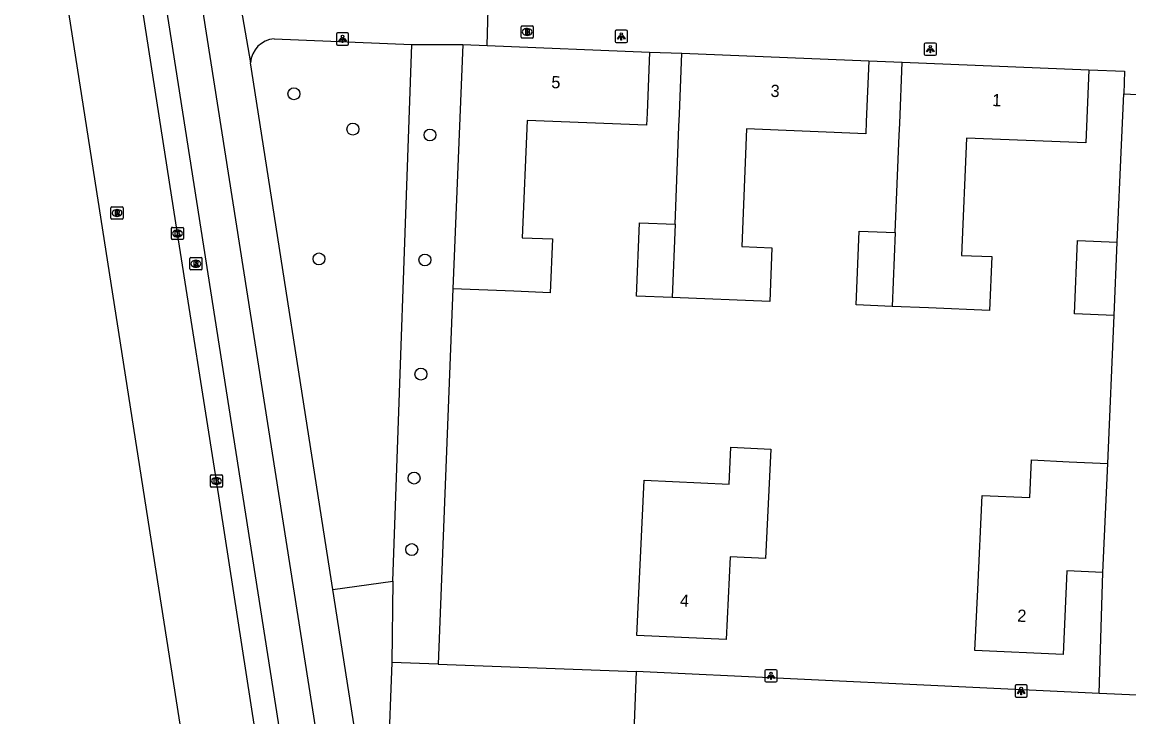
# Model space of a CAD drawing. Extents: x 160787 to 161428, y 386828 to 387483.
# Drawn here: x 160824.8 to 160915.3, y 387157.9 to 387214.7 of the extents above; entities that cross this region are included whole.
import ezdxf

# ---------------------------------------------------------------- set-up
doc = ezdxf.new("R2010")
doc.units = 0
for name, color, linetype in [('IMGEO_Boom', 7, 'Continuous'), ('IMGEO_Brandkraan', 7, 'Continuous'), ('IMGEO_Fietspad_gesloten', 7, 'Continuous'), ('IMGEO_Groenvoorziening', 7, 'Continuous'), ('IMGEO_Kolk', 7, 'Continuous'), ('IMGEO_Lichtpunt', 7, 'Continuous'), ('IMGEO_Muur', 7, 'Continuous'), ('IMGEO_Pand', 7, 'Continuous'), ('IMGEO_Pand_nummerreeks', 7, 'Continuous'), ('IMGEO_Rijbaan_lokaal_gesloten', 7, 'Continuous'), ('IMGEO_Rijbaan_lokaal_open', 7, 'Continuous'), ('IMGEO_Rioolput', 7, 'Continuous'), ('IMGEO_Voetpad_open', 7, 'Continuous')]:
    doc.layers.add(name, color=color, linetype=linetype)

msp = doc.modelspace()

# ---------------------------------------------------------------- linework, layer by layer
at = {"layer": 'IMGEO_Boom'}
for centre in [(160846.992, 387208.88), (160851.817, 387205.988), (160858.126, 387205.51), (160849.043, 387195.369), (160857.713, 387195.286), (160857.388, 387185.951), (160856.826, 387177.451), (160856.63, 387171.6)]:
    msp.add_circle(centre, 0.489, dxfattribs=at)
at = {"layer": 'IMGEO_Brandkraan'}
for p, q in [((160865.581, 387213.511), (160865.581, 387214.363)), ((160865.656, 387214.437), (160866.508, 387214.437)), ((160866.069, 387214.217), (160866.094, 387214.217)), ((160866.582, 387214.363), (160866.582, 387213.511)), ((160866.508, 387213.437), (160865.656, 387213.437)), ((160866.092, 387213.657), (160866.067, 387213.657))]:
    msp.add_line(p, q, dxfattribs=at)
for points in [[(160865.581, 387213.511), (160865.581, 387214.363)], [(160865.656, 387214.437), (160866.508, 387214.437)], [(160866.582, 387214.363), (160866.582, 387213.511)], [(160866.508, 387213.437), (160865.656, 387213.437)], [(160865.929, 387214.137), (160865.929, 387213.737), (160866.142, 387213.737)], [(160866.16, 387214.137), (160865.929, 387214.137)], [(160866.108, 387214.056), (160866.054, 387214.056), (160866.054, 387213.98)], [(160866.054, 387213.98), (160866.107, 387213.98)], [(160866.116, 387213.904), (160866.054, 387213.904), (160866.054, 387213.823)], [(160866.054, 387213.823), (160866.116, 387213.823)]]:
    msp.add_lwpolyline(points, dxfattribs=at)
for centre, radius, start, end in [((160865.658, 387214.361), 0.0765, 91.55205, 178.44795), ((160865.658, 387214.361), 0.0765, 91.55205, 178.44795), ((160866.506, 387214.361), 0.0765, 1.55205, 88.44795), ((160866.506, 387214.361), 0.0765, 1.55205, 88.44795), ((160865.658, 387213.513), 0.0765, 181.55205, 268.44795), ((160865.658, 387213.513), 0.0765, 181.55205, 268.44795), ((160866.109, 387214.018), 0.0379, 267.82845, 90.93552), ((160866.117, 387213.863), 0.0404, 269.87594, 90.50774), ((160866.148, 387213.988), 0.251, 268.66757, 293.53466), ((160866.164, 387213.992), 0.145, 59.4692, 91.53667), ((160866.189, 387214.039), 0.0922, 285.51372, 58.15012), ((160866.194, 387213.847), 0.105, 301.31148, 78.98903), ((160866.506, 387213.513), 0.0765, 271.55205, 358.44795), ((160866.506, 387213.513), 0.0765, 271.55205, 358.44795)]:
    msp.add_arc(centre, radius, start, end, dxfattribs=at)
for centre, major_axis, ratio, start_param, end_param in [((160866.068, 387213.937), (-0.387, 0.002), 0.722429, 4.712389, 7.853982), ((160866.093, 387213.937), (-0.39, 0.002), 0.717154, 1.570796, 4.712389)]:
    msp.add_ellipse(centre, major_axis=major_axis, ratio=ratio, start_param=start_param, end_param=end_param, dxfattribs=at)
at = {"layer": 'IMGEO_Fietspad_gesloten'}
for points in [[(160895.192, 386882.357), (160892.332, 386890.984), (160890.69, 386896.733), (160890.27, 386898.714), (160890.17, 386899.184), (160874.389, 386993.578), (160868.406, 387032.171), (160836.614, 387234.349), (160835.892, 387241.342), (160835.079, 387254.335)], [(160832.411, 387248.937), (160833.16, 387237.408), (160836.374, 387216.975), (160842.596, 387177.288), (160852.187, 387116.071), (160852.723, 387112.646)]]:
    msp.add_lwpolyline(points, dxfattribs=at)
at = {"layer": 'IMGEO_Groenvoorziening'}
for points in [[(160855.085, 387169.007), (160856.628, 387212.906)], [(160859.997, 387192.933), (160858.804, 387162.228)], [(160850.173, 387168.324), (160855.085, 387169.007)], [(160855.085, 387169.007), (160855.009, 387162.37)]]:
    msp.add_lwpolyline(points, dxfattribs=at)
at = {"layer": 'IMGEO_Kolk'}
for p, q in [((160837.037, 387197.957), (160837.889, 387197.957)), ((160836.962, 387197.031), (160836.962, 387197.883)), ((160837.473, 387197.177), (160837.448, 387197.177)), ((160837.45, 387197.737), (160837.475, 387197.737)), ((160837.963, 387197.883), (160837.963, 387197.031)), ((160837.889, 387196.957), (160837.037, 387196.957)), ((160840.156, 387176.784), (160840.156, 387177.636)), ((160840.231, 387177.71), (160841.083, 387177.71)), ((160840.644, 387177.49), (160840.669, 387177.49)), ((160841.157, 387177.636), (160841.157, 387176.784)), ((160841.083, 387176.71), (160840.231, 387176.71)), ((160840.667, 387176.93), (160840.642, 387176.93))]:
    msp.add_line(p, q, dxfattribs=at)
for points in [[(160837.037, 387197.957), (160837.889, 387197.957)], [(160836.962, 387197.031), (160836.962, 387197.883)], [(160837.283, 387197.657), (160837.406, 387197.657), (160837.406, 387197.506), (160837.536, 387197.657), (160837.7, 387197.657), (160837.554, 387197.506), (160837.707, 387197.257), (160837.555, 387197.257), (160837.47, 387197.421), (160837.406, 387197.354), (160837.406, 387197.257), (160837.283, 387197.257), (160837.283, 387197.657)], [(160837.963, 387197.883), (160837.963, 387197.031)], [(160837.889, 387196.957), (160837.037, 387196.957)], [(160840.156, 387176.784), (160840.156, 387177.636)], [(160840.231, 387177.71), (160841.083, 387177.71)], [(160840.477, 387177.41), (160840.6, 387177.41), (160840.6, 387177.259), (160840.73, 387177.41), (160840.894, 387177.41), (160840.748, 387177.259), (160840.901, 387177.01), (160840.749, 387177.01), (160840.664, 387177.174), (160840.6, 387177.107), (160840.6, 387177.01), (160840.477, 387177.01), (160840.477, 387177.41)], [(160841.157, 387177.636), (160841.157, 387176.784)], [(160841.083, 387176.71), (160840.231, 387176.71)]]:
    msp.add_lwpolyline(points, dxfattribs=at)
for centre, start, end in [((160837.039, 387197.881), 91.55205, 178.44795), ((160837.039, 387197.881), 91.55205, 178.44795), ((160837.887, 387197.881), 1.55205, 88.44795), ((160837.887, 387197.881), 1.55205, 88.44795), ((160837.039, 387197.033), 181.55205, 268.44795), ((160837.039, 387197.033), 181.55205, 268.44795), ((160837.887, 387197.033), 271.55205, 358.44795), ((160837.887, 387197.033), 271.55205, 358.44795), ((160840.233, 387177.634), 91.55205, 178.44795), ((160840.233, 387177.634), 91.55205, 178.44795), ((160841.081, 387177.634), 1.55205, 88.44795), ((160841.081, 387177.634), 1.55205, 88.44795), ((160840.233, 387176.786), 181.55205, 268.44795), ((160840.233, 387176.786), 181.55205, 268.44795), ((160841.081, 387176.786), 271.55205, 358.44795), ((160841.081, 387176.786), 271.55205, 358.44795)]:
    msp.add_arc(centre, 0.0765, start, end, dxfattribs=at)
for centre, major_axis, ratio, start_param, end_param in [((160837.449, 387197.457), (-0.387, 0.002), 0.722429, 4.712389, 7.853982), ((160837.474, 387197.457), (-0.39, 0.002), 0.717154, 1.570796, 4.712389), ((160840.643, 387177.21), (-0.387, 0.002), 0.722429, 4.712389, 7.853982), ((160840.668, 387177.21), (-0.39, 0.002), 0.717154, 1.570796, 4.712389)]:
    msp.add_ellipse(centre, major_axis=major_axis, ratio=ratio, start_param=start_param, end_param=end_param, dxfattribs=at)
at = {"layer": 'IMGEO_Lichtpunt'}
for p, q in [((160850.471, 387213.77), (160850.471, 387212.963)), ((160850.471, 387213.77), (160850.471, 387212.963)), ((160851.373, 387213.865), (160850.565, 387213.865)), ((160851.373, 387213.865), (160850.565, 387213.865)), ((160851.467, 387212.963), (160851.467, 387213.77)), ((160851.467, 387212.963), (160851.467, 387213.77)), ((160873.281, 387213.977), (160873.281, 387213.17)), ((160873.281, 387213.977), (160873.281, 387213.17)), ((160874.183, 387214.072), (160873.375, 387214.072)), ((160874.183, 387214.072), (160873.375, 387214.072)), ((160874.277, 387213.17), (160874.277, 387213.977)), ((160874.277, 387213.17), (160874.277, 387213.977)), ((160850.565, 387212.869), (160851.373, 387212.869)), ((160850.565, 387212.869), (160851.373, 387212.869)), ((160873.375, 387213.076), (160874.183, 387213.076)), ((160873.375, 387213.076), (160874.183, 387213.076)), ((160898.568, 387212.93), (160898.568, 387212.123)), ((160898.568, 387212.93), (160898.568, 387212.123)), ((160899.47, 387213.025), (160898.662, 387213.025)), ((160899.47, 387213.025), (160898.662, 387213.025)), ((160899.564, 387212.123), (160899.564, 387212.93)), ((160899.564, 387212.123), (160899.564, 387212.93)), ((160898.662, 387212.029), (160899.47, 387212.029)), ((160898.662, 387212.029), (160899.47, 387212.029)), ((160885.535, 387161.674), (160885.535, 387160.867)), ((160885.535, 387161.674), (160885.535, 387160.867)), ((160886.437, 387161.769), (160885.629, 387161.769)), ((160886.437, 387161.769), (160885.629, 387161.769)), ((160886.531, 387160.867), (160886.531, 387161.674)), ((160886.531, 387160.867), (160886.531, 387161.674)), ((160885.629, 387160.773), (160886.437, 387160.773)), ((160885.629, 387160.773), (160886.437, 387160.773)), ((160906.005, 387160.437), (160906.005, 387159.63)), ((160906.005, 387160.437), (160906.005, 387159.63)), ((160906.907, 387160.532), (160906.099, 387160.532)), ((160906.907, 387160.532), (160906.099, 387160.532)), ((160907.001, 387159.63), (160907.001, 387160.437)), ((160907.001, 387159.63), (160907.001, 387160.437)), ((160906.099, 387159.536), (160906.907, 387159.536)), ((160906.099, 387159.536), (160906.907, 387159.536))]:
    msp.add_line(p, q, dxfattribs=at)
for points in [[(160850.845, 387213.434), (160850.884, 387213.406), (160850.696, 387213.144), (160850.658, 387213.171), (160850.845, 387213.434)], [(160850.947, 387213.386), (160850.994, 387213.386), (160850.994, 387213.064), (160850.947, 387213.064), (160850.947, 387213.386)], [(160851.057, 387213.406), (160851.095, 387213.433), (160851.282, 387213.171), (160851.243, 387213.143), (160851.057, 387213.406)], [(160873.655, 387213.641), (160873.694, 387213.613), (160873.506, 387213.351), (160873.468, 387213.378), (160873.655, 387213.641)], [(160873.757, 387213.593), (160873.804, 387213.593), (160873.804, 387213.271), (160873.757, 387213.271), (160873.757, 387213.593)], [(160873.867, 387213.613), (160873.905, 387213.64), (160874.092, 387213.378), (160874.053, 387213.35), (160873.867, 387213.613)], [(160898.942, 387212.594), (160898.981, 387212.566), (160898.793, 387212.304), (160898.755, 387212.331), (160898.942, 387212.594)], [(160899.044, 387212.546), (160899.091, 387212.546), (160899.091, 387212.224), (160899.044, 387212.224), (160899.044, 387212.546)], [(160899.154, 387212.566), (160899.192, 387212.593), (160899.379, 387212.331), (160899.34, 387212.303), (160899.154, 387212.566)], [(160885.909, 387161.338), (160885.948, 387161.31), (160885.76, 387161.048), (160885.722, 387161.075), (160885.909, 387161.338)], [(160886.011, 387161.29), (160886.058, 387161.29), (160886.058, 387160.968), (160886.011, 387160.968), (160886.011, 387161.29)], [(160886.121, 387161.31), (160886.159, 387161.337), (160886.346, 387161.075), (160886.307, 387161.047), (160886.121, 387161.31)], [(160906.379, 387160.101), (160906.418, 387160.073), (160906.23, 387159.811), (160906.192, 387159.838), (160906.379, 387160.101)], [(160906.481, 387160.053), (160906.528, 387160.053), (160906.528, 387159.731), (160906.481, 387159.731), (160906.481, 387160.053)], [(160906.591, 387160.073), (160906.629, 387160.1), (160906.816, 387159.838), (160906.777, 387159.81), (160906.591, 387160.073)]]:
    msp.add_lwpolyline(points, dxfattribs=at)
for centre in [(160850.97, 387213.568), (160873.78, 387213.775), (160899.067, 387212.728), (160886.034, 387161.472), (160906.504, 387160.235)]:
    msp.add_circle(centre, 0.0994, dxfattribs=at)
for centre, start, end in [((160850.565, 387213.77), 90, 180), ((160850.565, 387213.77), 90, 180), ((160851.373, 387213.77), 0, 90), ((160851.373, 387213.77), 0, 90), ((160873.375, 387213.977), 90, 180), ((160873.375, 387213.977), 90, 180), ((160874.183, 387213.977), 0, 90), ((160874.183, 387213.977), 0, 90), ((160850.565, 387212.963), 180, 270), ((160850.565, 387212.963), 180, 270), ((160851.373, 387212.963), 270, 0), ((160851.373, 387212.963), 270, 360), ((160873.375, 387213.17), 180, 270), ((160873.375, 387213.17), 180, 270), ((160874.183, 387213.17), 270, 0), ((160874.183, 387213.17), 270, 360), ((160898.662, 387212.93), 90, 180), ((160898.662, 387212.93), 90, 180), ((160899.47, 387212.93), 0, 90), ((160899.47, 387212.93), 0, 90), ((160898.662, 387212.123), 180, 270), ((160898.662, 387212.123), 180, 270), ((160899.47, 387212.123), 270, 0), ((160899.47, 387212.123), 270, 360), ((160885.629, 387161.674), 90, 180), ((160885.629, 387161.674), 90, 180), ((160886.437, 387161.674), 0, 90), ((160886.437, 387161.674), 0, 90), ((160885.629, 387160.867), 180, 270), ((160885.629, 387160.867), 180, 270), ((160886.437, 387160.867), 270, 0), ((160886.437, 387160.867), 270, 360), ((160906.099, 387160.437), 90, 180), ((160906.099, 387160.437), 90, 180), ((160906.907, 387160.437), 0, 90), ((160906.907, 387160.437), 0, 90), ((160906.099, 387159.63), 180, 270), ((160906.099, 387159.63), 180, 270), ((160906.907, 387159.63), 270, 0), ((160906.907, 387159.63), 270, 360)]:
    msp.add_arc(centre, 0.0946, start, end, dxfattribs=at)
at = {"layer": 'IMGEO_Muur'}
msp.add_lwpolyline([(160914.724, 387204.715), (160914.892, 387208.871)], dxfattribs=at)
at = {"layer": 'IMGEO_Pand'}
for points in [[(160860.807, 387212.918), (160859.997, 387192.933)], [(160860.807, 387212.918), (160862.811, 387212.837)], [(160862.811, 387212.837), (160876.089, 387212.298)], [(160876.089, 387212.298), (160875.887, 387207.303), (160875.846, 387206.302), (160866.068, 387206.699), (160865.68, 387197.108), (160868.14, 387197.009), (160867.961, 387192.611), (160864.993, 387192.731), (160859.997, 387192.933)], [(160894.025, 387211.588), (160893.823, 387206.593), (160893.783, 387205.605), (160884.035, 387206.001), (160883.646, 387196.386), (160886.106, 387196.287), (160885.927, 387191.888), (160877.934, 387192.213)], [(160878.177, 387198.208), (160878.501, 387206.194), (160878.542, 387207.212), (160878.744, 387212.207)], [(160878.744, 387212.207), (160894.025, 387211.588)], [(160912.045, 387210.839), (160911.802, 387204.856), (160902.019, 387205.253), (160901.631, 387195.663), (160904.091, 387195.564), (160903.912, 387191.165), (160898.917, 387191.368), (160895.955, 387191.488)], [(160896.2, 387197.536), (160896.523, 387205.494), (160896.562, 387206.463), (160896.765, 387211.458)], [(160896.765, 387211.458), (160912.045, 387210.839)], [(160877.934, 387192.213), (160875.016, 387192.331), (160875.259, 387198.326), (160878.177, 387198.208)], [(160878.177, 387198.208), (160877.934, 387192.213)], [(160895.955, 387191.488), (160893.011, 387191.607), (160893.256, 387197.655), (160896.2, 387197.536)], [(160896.2, 387197.536), (160895.955, 387191.488)], [(160914.106, 387190.757), (160910.869, 387190.887), (160911.111, 387196.884), (160914.348, 387196.743)], [(160914.106, 387190.757), (160914.348, 387196.743)], [(160885.588, 387170.881), (160882.688, 387171.017), (160882.369, 387164.24), (160875.065, 387164.584), (160875.661, 387177.27), (160882.613, 387176.943), (160882.755, 387179.963), (160886.008, 387179.81), (160885.588, 387170.881)], [(160913.174, 387169.721), (160910.252, 387169.859), (160909.93, 387163.006), (160902.716, 387163.345), (160902.951, 387168.34), (160903.312, 387176.031), (160907.216, 387175.847), (160907.361, 387178.927), (160910.442, 387178.781), (160913.593, 387178.632)], [(160913.174, 387169.721), (160913.593, 387178.632)], [(160855.009, 387162.37), (160854.714, 387154.505)], [(160858.804, 387162.228), (160855.009, 387162.37)], [(160858.804, 387162.228), (160874.993, 387161.62)], [(160874.993, 387161.62), (160874.296, 387143.28)]]:
    msp.add_lwpolyline(points, dxfattribs=at)
at = {"layer": 'IMGEO_Rijbaan_lokaal_gesloten'}
for points in [[(160850.801, 387112.345), (160850.314, 387115.477), (160846.832, 387137.716), (160843.786, 387156.959), (160840.657, 387177.21), (160837.463, 387197.457), (160834.472, 387216.74), (160831.427, 387235.974), (160829.724, 387246.655)], [(160824.752, 387239.782), (160835.704, 387169.823), (160841.78, 387131.053)]]:
    msp.add_lwpolyline(points, dxfattribs=at)
at = {"layer": 'IMGEO_Rijbaan_lokaal_open'}
for points in [[(160862.811, 387212.837), (160862.892, 387215.805)], [(160876.089, 387212.298), (160878.744, 387212.207)], [(160894.025, 387211.588), (160896.765, 387211.458)], [(160912.045, 387210.839), (160914.967, 387210.721), (160914.892, 387208.871)], [(160914.892, 387208.871), (160920.768, 387208.584)], [(160912.884, 387159.831), (160874.993, 387161.62)], [(160916.006, 387159.69), (160912.884, 387159.831)]]:
    msp.add_lwpolyline(points, dxfattribs=at)
at = {"layer": 'IMGEO_Rioolput'}
for p, q in [((160832.02, 387198.703), (160832.02, 387199.555)), ((160832.095, 387199.629), (160832.947, 387199.629)), ((160832.531, 387198.849), (160832.506, 387198.849)), ((160832.508, 387199.409), (160832.533, 387199.409)), ((160833.021, 387199.555), (160833.021, 387198.703)), ((160832.947, 387198.629), (160832.095, 387198.629)), ((160838.469, 387194.553), (160838.469, 387195.405)), ((160838.544, 387195.479), (160839.396, 387195.479)), ((160838.957, 387195.259), (160838.982, 387195.259)), ((160839.47, 387195.405), (160839.47, 387194.553)), ((160839.396, 387194.479), (160838.544, 387194.479)), ((160838.98, 387194.699), (160838.955, 387194.699))]:
    msp.add_line(p, q, dxfattribs=at)
for points in [[(160832.02, 387198.703), (160832.02, 387199.555)], [(160832.095, 387199.629), (160832.947, 387199.629)], [(160832.609, 387199.327), (160832.357, 387199.329), (160832.357, 387198.929)], [(160832.357, 387198.929), (160832.481, 387198.929), (160832.481, 387199.091), (160832.492, 387199.091)], [(160832.535, 387199.248), (160832.481, 387199.248), (160832.481, 387199.167)], [(160832.481, 387199.167), (160832.533, 387199.167)], [(160832.539, 387199.062), (160832.61, 387198.929), (160832.75, 387198.929), (160832.685, 387199.055)], [(160833.021, 387199.555), (160833.021, 387198.703)], [(160832.947, 387198.629), (160832.095, 387198.629)], [(160838.469, 387194.553), (160838.469, 387195.405)], [(160838.544, 387195.479), (160839.396, 387195.479)], [(160839.058, 387195.177), (160838.806, 387195.179), (160838.806, 387194.779)], [(160839.47, 387195.405), (160839.47, 387194.553)], [(160839.396, 387194.479), (160838.544, 387194.479)], [(160838.806, 387194.779), (160838.93, 387194.779), (160838.93, 387194.941), (160838.941, 387194.941)], [(160838.984, 387195.098), (160838.93, 387195.098), (160838.93, 387195.017)], [(160838.93, 387195.017), (160838.982, 387195.017)], [(160838.988, 387194.912), (160839.059, 387194.779), (160839.199, 387194.779), (160839.134, 387194.905)]]:
    msp.add_lwpolyline(points, dxfattribs=at)
for centre, radius, start, end in [((160832.097, 387199.553), 0.0765, 91.55205, 178.44795), ((160832.097, 387199.553), 0.0765, 91.55205, 178.44795), ((160832.491, 387199.038), 0.0533, 26.02933, 88.69889), ((160832.517, 387199.356), 0.19, 274.7715, 282.96867), ((160832.541, 387199.152), 0.0964, 77.00612, 93.18647), ((160832.555, 387199.209), 0.0378, 276.66336, 79.67722), ((160832.608, 387199.217), 0.109, 350.36119, 89.41601), ((160832.606, 387199.217), 0.112, 277.58423, 350.98172), ((160832.59, 387199.002), 0.108, 29.51342, 73.79051), ((160832.945, 387199.553), 0.0765, 1.55205, 88.44795), ((160832.945, 387199.553), 0.0765, 1.55205, 88.44795), ((160832.097, 387198.705), 0.0765, 181.55205, 268.44795), ((160832.097, 387198.705), 0.0765, 181.55205, 268.44795), ((160832.945, 387198.705), 0.0765, 271.55205, 358.44795), ((160832.945, 387198.705), 0.0765, 271.55205, 358.44795), ((160838.546, 387195.403), 0.0765, 91.55205, 178.44795), ((160838.546, 387195.403), 0.0765, 91.55205, 178.44795), ((160839.057, 387195.067), 0.109, 350.36119, 89.41601), ((160839.394, 387195.403), 0.0765, 1.55205, 88.44795), ((160839.394, 387195.403), 0.0765, 1.55205, 88.44795), ((160838.546, 387194.555), 0.0765, 181.55205, 268.44795), ((160838.546, 387194.555), 0.0765, 181.55205, 268.44795), ((160838.94, 387194.888), 0.0533, 26.02933, 88.69889), ((160838.966, 387195.206), 0.19, 274.7715, 282.96867), ((160838.99, 387195.002), 0.0964, 77.00612, 93.18647), ((160839.004, 387195.059), 0.0378, 276.66336, 79.67722), ((160839.055, 387195.067), 0.112, 277.58423, 350.98172), ((160839.039, 387194.852), 0.108, 29.51342, 73.79051), ((160839.394, 387194.555), 0.0765, 271.55205, 358.44795), ((160839.394, 387194.555), 0.0765, 271.55205, 358.44795)]:
    msp.add_arc(centre, radius, start, end, dxfattribs=at)
for centre, major_axis, ratio, start_param, end_param in [((160832.507, 387199.129), (-0.387, 0.002), 0.722429, 4.712389, 7.853982), ((160832.532, 387199.129), (-0.39, 0.002), 0.717154, 1.570796, 4.712389), ((160838.956, 387194.979), (-0.387, 0.002), 0.722429, 4.712389, 7.853982), ((160838.981, 387194.979), (-0.39, 0.002), 0.717154, 1.570796, 4.712389)]:
    msp.add_ellipse(centre, major_axis=major_axis, ratio=ratio, start_param=start_param, end_param=end_param, dxfattribs=at)
at = {"layer": 'IMGEO_Voetpad_open'}
for points in [[(160842.556, 387216.426), (160843.436, 387211.425)], [(160845.381, 387213.384), (160856.628, 387212.906)], [(160856.628, 387212.906), (160860.807, 387212.918)], [(160850.173, 387168.324), (160843.436, 387211.425)], [(160914.348, 387196.743), (160914.724, 387204.715), (160914.892, 387208.871)], [(160913.593, 387178.632), (160914.106, 387190.757)], [(160912.884, 387159.831), (160913.174, 387169.721)], [(160853.962, 387144.085), (160850.173, 387168.324)]]:
    msp.add_lwpolyline(points, dxfattribs=at)
msp.add_arc((160845.554, 387211.268), 2.123, 94.66067, 175.75027, dxfattribs=at)

# ---------------------------------------------------------------- texts
at = {"layer": 'IMGEO_Pand_nummerreeks'}
for s, rotation, p in [('5', 357.67675, (160868.04, 387209.342)), ('3', 357.68034, (160885.977, 387208.632)), ('1', 357.68019, (160904.112, 387207.878)), ('4', 357.30351, (160878.56, 387166.942)), ('2', 357.3071, (160906.164, 387165.705))]:
    msp.add_text(s, height=1, rotation=rotation, dxfattribs=at).set_placement(p)

doc.saveas('drawing.dxf')
